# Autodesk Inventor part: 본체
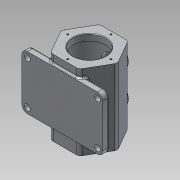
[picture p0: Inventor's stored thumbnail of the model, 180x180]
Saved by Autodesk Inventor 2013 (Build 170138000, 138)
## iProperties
Created: 2021-06
Part Number: 본체
Material: 알루미늄 6061
Document SubType Name: Modeling
Designer: cad21
Density: 2.71 g/cm^3
Mass: 1501.03 g
Surface Area: 1102.04 cm^2
Volume: 553.886 cm^3
Author: cad21
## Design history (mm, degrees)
sketch "스케치1"
  geometry: L1 (-26.25, -45.466)-(-52.5, 0); L2 (-52.5, 0)-(-26.25, 45.466); L3 (-26.25, 45.466)-(26.25, 45.466); L4 (26.25, 45.466)-(52.5, 0); L5 (52.5, 0)-(26.25, -45.466); L6 (26.25, -45.466)-(-26.25, -45.466); L7 (-73.5, 0)-(73.5, 0) reference; L8 (0, -63.653)-(0, 63.653) reference; 1 further point
  constraints: 12 end point, 1 parallel, 13 other
  dimensions: "d0" = 105 distance of L4.end L1.end
extrude "돌출1" new body sketch "스케치1" stored distance "d2" = 140; taper "d3" = 0 deg
sketch "스케치13"
  geometry: L1 (73.5, 0)-(-73.5, 0) reference; L2 (0, -98)-(0, 98) reference; L3 (52.5, 70)-(26.25, 70) reference; L4 (-26.25, -70)-(26.25, -70) reference; C1 r 20 at (0, -30); C2 r 20 at (0, 30); 1 further point
  constraints: 2 centre point, 2 point on line
  dimensions: "d60" = 40 diameter of C1; "d65" = 40 distance from line of L4 C1.centre; "d66" = 40 diameter of C2; "d67" = 60 distance of C1.centre C2.centre
extrude "돌출10" join sketch "스케치13" distance "d63" = 52.5; taper "d64" = 0 deg
node "작업 평면1"
sketch "스케치20"
  geometry: 1 further point
sketch "스케치14"
  geometry: C1 r 20 at (0, 0) reference; C2 r 12.5 at (0, 0); C3 r 12.5 at (0, -60); 1 further point
  constraints: 2 centre point, 1 coincident
  dimensions: "d68" = 25 diameter of C2; "d69" = 25 diameter of C3; "d70" = 60 distance of C3.centre C2.centre
extrude "돌출11" cut sketch "스케치14" distance "d71" = 30; taper "d72" = 0 deg
sketch "스케치15"
  geometry: L1 (-73.5, -30)-(73.5, -30) reference; L2 (0, 68)-(0, -128) reference; C1 r 20 at (0, 0) reference; C2 r 15 at (0, 0); C3 r 15 at (0, -60); 1 further point
  constraints: 2 centre point, 1 coincident, 1 point on line
  dimensions: "d73" = 30 diameter of C2; "d74" = 30 diameter of C3; "d75" = 60 distance of C1.centre C3.centre
extrude "돌출12" cut sketch "스케치15" distance "d76" = 8; taper "d77" = 0 deg
sketch "스케치9"
  geometry: C1 r 30 at (0, 0) reference; C2 r 37.5 at (0, 0)
  constraints: 1 centre point, 1 coincident
  dimensions: "d30" = 75 diameter of C2
extrude "돌출8" cut sketch "스케치9" stored distance "d31" = 116; taper "d32" = 0 deg
sketch "스케치10"
  geometry: C1 r 37.5 at (0, 0) reference; C2 r 37.5 at (0, 0); C3 r 30 at (0, 0)
  constraints: 2 centre point, 2 coincident
  dimensions: "d33" = 75 diameter of C2; "d34" = 60 diameter of C3
extrude "돌출9" join sketch "스케치10" distance "d35" = 12; taper "d36" = 0 deg
sketch "스케치16"
  geometry: L1 (69.448, -69.448)-(-63.488, 63.488); L2 (96.036, 0)-(-90.076, 0) reference; L3 (0, -96.932)-(0, 95.458) reference; L4 (-49.171, -49.171)-(67.973, 67.973); C1 r 30 at (0, 0) reference; A1 r 40 centre (0, 0) between (28.284, 28.284) and (28.284, -28.284); 2 further points
  constraints: 6 point on line, 4 end point, 4 point on circle, 1 centre point, 1 coincident, 1 perpendicular
  dimensions: "d79" = 45 deg angle of L3 L1; "d80" = 80 diameter of A1
hole "구멍4" sketch "스케치16" at (28.284, 28.284), (28.284, -28.284), (-28.284, -28.284), (-28.284, 28.284) diameter "d81" = 3.242; stored, may be unused: countersink angle "d85" = 90 deg, drill point angle "d87" = 118 deg; dims "d82" = 8, "d83" = 4, "d84" = 2, "d86" = 10
sketch "스케치17"
  geometry: L1 (-73.5, 0)-(73.5, 0) reference; L2 (0, -70.5)-(0, 73) reference; C1 r 30 at (0, 0) reference; A1 r 40 centre (0, 0) between (0, 40) and (-40, 0); 2 further points
  constraints: 4 point on circle, 4 point on line, 1 centre point, 1 coincident
  dimensions: "d88" = 80 diameter of A1
hole "구멍5" sketch "스케치17" at (0, 40), (-40, 0), (40, 0), (0, -40) diameter "d89" = 3.242; stored, may be unused: countersink angle "d93" = 90 deg, drill point angle "d95" = 118 deg; dims "d90" = 8, "d91" = 4, "d92" = 2, "d94" = 10
fillet "모깎기2" dims "d101" = 3, "d102" = 5
sketch "스케치21"
  geometry: L1 (-75, -45)-(75, -45); L2 (75, -45)-(75, 55); L3 (75, 55)-(-75, 55); L4 (-75, 55)-(-75, -45); L5 (147.061, 0)-(-84.316, 0) reference; L6 (0, -98)-(0, 98) reference; L7 (-26.25, -70)-(26.25, -70) reference; 3 further points
  constraints: 8 end point, 2 parallel, 1 horizontal, 1 perpendicular, 1 other
  dimensions: "d111" = 150 distance of L1.start L1.end; "d113" = 100 distance of L3.end L1.start; "d114" = 25 distance between parallel lines of L7 L1
extrude "돌출14" join sketch "스케치21" distance "d115" = 12; taper "d116" = 0 deg
chamfer "모따기1" distance "d103" = 1; stored, may be unused: second distance "d104" = 2, angle "d105" = 45 deg
fillet "모깎기3" dims "d117" = 8, "d118" = 3, "d119" = 10
sketch "스케치22"
  geometry: C1 r 5.5 at (-65, 35); C2 r 5.5 at (-65, -45); A1 r 7 centre (-65, 35) between (-65, 42) and (-72, 35) reference; A2 r 7 centre (-65, -45) between (-72, -45) and (-65, -52) reference; 1 further point
  constraints: 2 centre point, 2 coincident
  dimensions: "d120" = 11 diameter of C1; "d121" = 11 diameter of C2
extrude "돌출15" cut sketch "스케치22" distance "d122" = 12; taper "d123" = 0 deg
sketch "스케치23"
  geometry: L1 (75, -45)-(75, 35) reference; L2 (65, 45)-(32.293, 45) reference; 2 further points
  constraints: 1 other
  dimensions: "d124" = 14 distance from line of point (61, -5) L1; "d125" = 50 distance from line of L2 point (61, -5)
feature "엠보싱2" sketch "스케치23" dims "d0" = 105, "d126" = 0.5, "d127" = 0
node "솔리드1"
mirror "대칭3"
mirror "대칭5"
